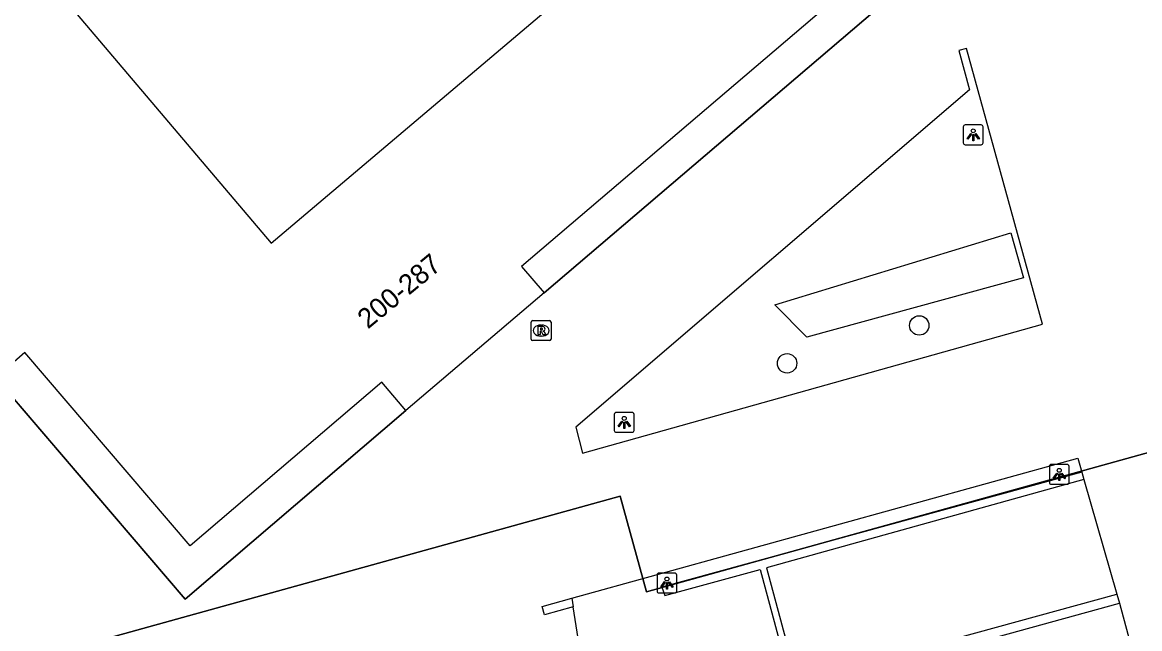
# Model space of a CAD drawing. Extents: x 159053 to 160041, y 380450 to 381422.
# Drawn here: x 159185.4 to 159241.7, y 381155.2 to 381185.8 of the extents above; entities that cross this region are included whole.
import ezdxf

# ---------------------------------------------------------------- set-up
doc = ezdxf.new("R2010")
doc.units = 0
for name, color, linetype in [('IMGEO_Boom', 7, 'Continuous'), ('IMGEO_Haag', 7, 'Continuous'), ('IMGEO_Lichtpunt', 7, 'Continuous'), ('IMGEO_Muur', 7, 'Continuous'), ('IMGEO_Pand', 7, 'Continuous'), ('IMGEO_Pand_nummerreeks', 7, 'Continuous'), ('IMGEO_Pand_overbouw', 7, 'Continuous'), ('IMGEO_Pand_vergunning_verleend', 7, 'Continuous'), ('IMGEO_Rijbaan_lokaal_open', 7, 'Continuous'), ('IMGEO_Rioolput', 7, 'Continuous')]:
    doc.layers.add(name, color=color, linetype=linetype)

msp = doc.modelspace()

# ---------------------------------------------------------------- linework, layer by layer
at = {"layer": 'IMGEO_Boom'}
for centre in [(159230.562, 381170.511), (159223.901, 381168.603)]:
    msp.add_circle(centre, 0.489, dxfattribs=at)
at = {"layer": 'IMGEO_Haag'}
msp.add_lwpolyline([(159235.174, 381175.183), (159235.815, 381172.914), (159224.894, 381169.919), (159223.289, 381171.556), (159235.174, 381175.183)], dxfattribs=at)
at = {"layer": 'IMGEO_Lichtpunt'}
for p, q in [((159233.683, 381180.621), (159232.875, 381180.621)), ((159233.683, 381180.621), (159232.875, 381180.621)), ((159232.781, 381180.526), (159232.781, 381179.719)), ((159232.781, 381180.526), (159232.781, 381179.719)), ((159233.777, 381179.719), (159233.777, 381180.526)), ((159233.777, 381179.719), (159233.777, 381180.526)), ((159232.875, 381179.625), (159233.683, 381179.625)), ((159232.875, 381179.625), (159233.683, 381179.625)), ((159215.195, 381166.028), (159215.195, 381165.221)), ((159215.195, 381166.028), (159215.195, 381165.221)), ((159216.097, 381166.123), (159215.289, 381166.123)), ((159216.097, 381166.123), (159215.289, 381166.123)), ((159216.191, 381165.221), (159216.191, 381166.028)), ((159216.191, 381165.221), (159216.191, 381166.028)), ((159215.289, 381165.127), (159216.097, 381165.127)), ((159215.289, 381165.127), (159216.097, 381165.127)), ((159237.118, 381163.408), (159237.118, 381162.601)), ((159237.118, 381163.408), (159237.118, 381162.601)), ((159238.02, 381163.503), (159237.212, 381163.503)), ((159238.02, 381163.503), (159237.212, 381163.503)), ((159238.114, 381162.601), (159238.114, 381163.408)), ((159238.114, 381162.601), (159238.114, 381163.408)), ((159237.212, 381162.507), (159238.02, 381162.507)), ((159237.212, 381162.507), (159238.02, 381162.507)), ((159217.347, 381157.93), (159217.347, 381157.123)), ((159217.347, 381157.93), (159217.347, 381157.123)), ((159218.249, 381158.025), (159217.441, 381158.025)), ((159218.249, 381158.025), (159217.441, 381158.025)), ((159218.343, 381157.123), (159218.343, 381157.93)), ((159218.343, 381157.123), (159218.343, 381157.93)), ((159217.441, 381157.029), (159218.249, 381157.029)), ((159217.441, 381157.029), (159218.249, 381157.029))]:
    msp.add_line(p, q, dxfattribs=at)
for points in [[(159233.155, 381180.19), (159233.194, 381180.162), (159233.006, 381179.9), (159232.968, 381179.927), (159233.155, 381180.19)], [(159233.257, 381180.142), (159233.304, 381180.142), (159233.304, 381179.82), (159233.257, 381179.82), (159233.257, 381180.142)], [(159233.367, 381180.162), (159233.405, 381180.189), (159233.592, 381179.927), (159233.553, 381179.899), (159233.367, 381180.162)], [(159215.569, 381165.692), (159215.608, 381165.664), (159215.42, 381165.402), (159215.382, 381165.429), (159215.569, 381165.692)], [(159215.671, 381165.644), (159215.718, 381165.644), (159215.718, 381165.322), (159215.671, 381165.322), (159215.671, 381165.644)], [(159215.781, 381165.664), (159215.819, 381165.691), (159216.006, 381165.429), (159215.967, 381165.401), (159215.781, 381165.664)], [(159237.492, 381163.072), (159237.531, 381163.044), (159237.343, 381162.782), (159237.305, 381162.809), (159237.492, 381163.072)], [(159237.594, 381163.024), (159237.641, 381163.024), (159237.641, 381162.702), (159237.594, 381162.702), (159237.594, 381163.024)], [(159237.704, 381163.044), (159237.742, 381163.071), (159237.929, 381162.809), (159237.89, 381162.781), (159237.704, 381163.044)], [(159217.721, 381157.594), (159217.76, 381157.566), (159217.572, 381157.304), (159217.534, 381157.331), (159217.721, 381157.594)], [(159217.823, 381157.546), (159217.87, 381157.546), (159217.87, 381157.224), (159217.823, 381157.224), (159217.823, 381157.546)], [(159217.933, 381157.566), (159217.971, 381157.593), (159218.158, 381157.331), (159218.119, 381157.303), (159217.933, 381157.566)]]:
    msp.add_lwpolyline(points, dxfattribs=at)
for centre in [(159233.28, 381180.324), (159215.694, 381165.826), (159237.617, 381163.206), (159217.846, 381157.728)]:
    msp.add_circle(centre, 0.0994, dxfattribs=at)
for centre, start, end in [((159232.875, 381180.526), 90, 180), ((159232.875, 381180.526), 90, 180), ((159233.683, 381180.526), 0, 90), ((159233.683, 381180.526), 0, 90), ((159232.875, 381179.719), 180, 270), ((159232.875, 381179.719), 180, 270), ((159233.683, 381179.719), 270, 0), ((159233.683, 381179.719), 270, 360), ((159215.289, 381166.028), 90, 180), ((159215.289, 381166.028), 90, 180), ((159216.097, 381166.028), 0, 90), ((159216.097, 381166.028), 0, 90), ((159215.289, 381165.221), 180, 270), ((159215.289, 381165.221), 180, 270), ((159216.097, 381165.221), 270, 0), ((159216.097, 381165.221), 270, 360), ((159237.212, 381163.408), 90, 180), ((159237.212, 381163.408), 90, 180), ((159238.02, 381163.408), 0, 90), ((159238.02, 381163.408), 0, 90), ((159237.212, 381162.601), 180, 270), ((159237.212, 381162.601), 180, 270), ((159238.02, 381162.601), 270, 0), ((159238.02, 381162.601), 270, 360), ((159217.441, 381157.93), 90, 180), ((159217.441, 381157.93), 90, 180), ((159218.249, 381157.93), 0, 90), ((159218.249, 381157.93), 0, 90), ((159217.441, 381157.123), 180, 270), ((159217.441, 381157.123), 180, 270), ((159218.249, 381157.123), 270, 0), ((159218.249, 381157.123), 270, 360)]:
    msp.add_arc(centre, 0.0946, start, end, dxfattribs=at)
at = {"layer": 'IMGEO_Muur'}
for points in [[(159238.752, 381163.12), (159217.582, 381157.313), (159217.741, 381156.904), (159222.547, 381158.213), (159224.092, 381152.463), (159219.287, 381151.075), (159219.363, 381150.64), (159240.646, 381156.513)], [(159238.752, 381163.12), (159238.859, 381162.738)], [(159238.859, 381162.738), (159222.863, 381158.29), (159224.406, 381152.545), (159240.524, 381156.966)], [(159240.524, 381156.966), (159240.646, 381156.513)], [(159213.126, 381156.324), (159211.682, 381155.929), (159211.562, 381156.348), (159213.057, 381156.762)], [(159213.057, 381156.762), (159213.126, 381156.324)]]:
    msp.add_lwpolyline(points, dxfattribs=at)
at = {"layer": 'IMGEO_Pand'}
for points in [[(159204.697, 381166.217), (159203.481, 381167.645), (159193.829, 381159.398), (159185.489, 381169.145), (159184.952, 381168.684), (159183.585, 381170.288), (159183.438, 381170.172), (159181.985, 381171.85), (159182.128, 381171.975), (159179.119, 381175.513), (159179.666, 381175.981), (159173.652, 381183.04), (159171.34, 381185.754), (159208.994, 381217.897), (159211.279, 381215.206), (159213.579, 381212.498), (159213.685, 381212.589), (159231.66, 381191.536), (159210.522, 381173.486), (159211.653, 381172.164)], [(159216.984, 381190.828), (159206.446, 381203.264), (159187.373, 381187.101), (159197.911, 381174.666), (159216.984, 381190.828)], [(159211.653, 381172.164), (159204.697, 381166.217)]]:
    msp.add_lwpolyline(points, dxfattribs=at)
at = {"layer": 'IMGEO_Pand_overbouw'}
for points in [[(159209.242, 381220.546), (159168.702, 381185.792), (159193.566, 381156.711), (159204.697, 381166.217), (159203.481, 381167.645), (159193.829, 381159.398), (159185.489, 381169.145), (159184.952, 381168.684), (159183.585, 381170.288), (159183.438, 381170.172), (159181.985, 381171.85), (159182.128, 381171.975), (159179.119, 381175.513), (159179.666, 381175.981), (159173.652, 381183.04), (159171.34, 381185.754), (159208.994, 381217.897)], [(159231.66, 381191.536), (159210.522, 381173.486), (159211.653, 381172.164), (159234.166, 381191.389)]]:
    msp.add_lwpolyline(points, dxfattribs=at)
for points in [[(159216.984, 381190.828), (159206.446, 381203.264), (159187.373, 381187.101), (159197.911, 381174.666)], [(159249.617, 381146.417), (159253.067, 381147.375), (159252.059, 381151.007), (159248.609, 381150.05), (159244.524, 381164.774), (159216.821, 381157.087), (159215.484, 381161.905), (159146.712, 381142.823), (159144.149, 381142.112), (159127.074, 381137.375), (159127.322, 381136.481), (159127.96, 381134.183), (159128.847, 381130.986), (159129.855, 381127.353), (159132.702, 381117.091), (159133.413, 381114.528), (159135.79, 381105.961), (159251.903, 381138.179)]]:
    msp.add_lwpolyline(points, close=True, dxfattribs=at)
at = {"layer": 'IMGEO_Pand_vergunning_verleend'}
msp.add_lwpolyline([(159251.903, 381138.179), (159135.79, 381105.961), (159133.413, 381114.528), (159130.137, 381113.619), (159129.426, 381116.182), (159132.702, 381117.091), (159129.855, 381127.353), (159126.405, 381126.396), (159125.397, 381130.029), (159128.847, 381130.986), (159127.074, 381137.375), (159144.149, 381142.112), (159143.24, 381145.388), (159145.803, 381146.1), (159146.712, 381142.823), (159215.484, 381161.905), (159216.821, 381157.087), (159244.524, 381164.774), (159248.609, 381150.05), (159252.059, 381151.007), (159253.067, 381147.375), (159249.617, 381146.417), (159251.903, 381138.179)], dxfattribs=at)
at = {"layer": 'IMGEO_Rijbaan_lokaal_open'}
for points in [[(159212.743, 381216.45), (159234.166, 381191.389), (159211.653, 381172.164)], [(159232.941, 381184.475), (159232.555, 381184.369), (159233.101, 381182.389), (159213.252, 381165.38), (159213.587, 381164.073), (159236.77, 381170.574), (159232.941, 381184.475)], [(159204.697, 381166.217), (159193.566, 381156.711), (159175.262, 381178.12)], [(159213.057, 381156.762), (159238.557, 381163.817), (159238.752, 381163.12)], [(159238.859, 381162.738), (159240.524, 381156.966)], [(159240.646, 381156.513), (159241.419, 381153.64), (159241.021, 381153.516), (159240.888, 381153.929), (159225.962, 381146.043), (159224.336, 381148.322), (159214.807, 381145.673), (159213.126, 381156.324)]]:
    msp.add_lwpolyline(points, dxfattribs=at)
at = {"layer": 'IMGEO_Rioolput'}
for p, q in [((159211.007, 381169.828), (159211.007, 381170.68)), ((159211.082, 381170.754), (159211.934, 381170.754)), ((159211.495, 381170.534), (159211.52, 381170.534)), ((159212.008, 381170.68), (159212.008, 381169.828)), ((159211.518, 381169.974), (159211.493, 381169.974)), ((159211.934, 381169.754), (159211.082, 381169.754))]:
    msp.add_line(p, q, dxfattribs=at)
for points in [[(159211.007, 381169.828), (159211.007, 381170.68)], [(159211.082, 381170.754), (159211.934, 381170.754)], [(159211.596, 381170.452), (159211.344, 381170.454), (159211.344, 381170.054)], [(159212.008, 381170.68), (159212.008, 381169.828)], [(159211.344, 381170.054), (159211.468, 381170.054), (159211.468, 381170.216), (159211.479, 381170.216)], [(159211.522, 381170.373), (159211.468, 381170.373), (159211.468, 381170.292)], [(159211.468, 381170.292), (159211.52, 381170.292)], [(159211.526, 381170.187), (159211.597, 381170.054), (159211.737, 381170.054), (159211.672, 381170.18)], [(159211.934, 381169.754), (159211.082, 381169.754)]]:
    msp.add_lwpolyline(points, dxfattribs=at)
for centre, radius, start, end in [((159211.084, 381170.678), 0.0765, 91.552, 178.448), ((159211.084, 381170.678), 0.0765, 91.552, 178.448), ((159211.595, 381170.342), 0.109, 350.3612, 89.416), ((159211.932, 381170.678), 0.0765, 1.552, 88.448), ((159211.932, 381170.678), 0.0765, 1.552, 88.448), ((159211.478, 381170.163), 0.0533, 26.0293, 88.6989), ((159211.504, 381170.481), 0.19, 274.7715, 282.9687), ((159211.528, 381170.277), 0.0964, 77.0061, 93.1865), ((159211.542, 381170.334), 0.0378, 276.6634, 79.6772), ((159211.593, 381170.342), 0.112, 277.5842, 350.9817), ((159211.577, 381170.127), 0.108, 29.5134, 73.7905), ((159211.084, 381169.83), 0.0765, 181.552, 268.448), ((159211.084, 381169.83), 0.0765, 181.552, 268.448), ((159211.932, 381169.83), 0.0765, 271.552, 358.448), ((159211.932, 381169.83), 0.0765, 271.552, 358.448)]:
    msp.add_arc(centre, radius, start, end, dxfattribs=at)
for centre, major_axis, ratio, start_param, end_param in [((159211.494, 381170.254), (-0.387, 0.002), 0.722429, 4.712389, 7.853982), ((159211.519, 381170.254), (-0.39, 0.002), 0.717154, 1.570796, 4.712389)]:
    msp.add_ellipse(centre, major_axis=major_axis, ratio=ratio, start_param=start_param, end_param=end_param, dxfattribs=at)

# ---------------------------------------------------------------- texts
at = {"layer": 'IMGEO_Pand_nummerreeks'}
msp.add_text('200-287', height=1, rotation=39.5903, dxfattribs=at).set_placement((159202.778, 381170.303))

doc.saveas('drawing.dxf')
